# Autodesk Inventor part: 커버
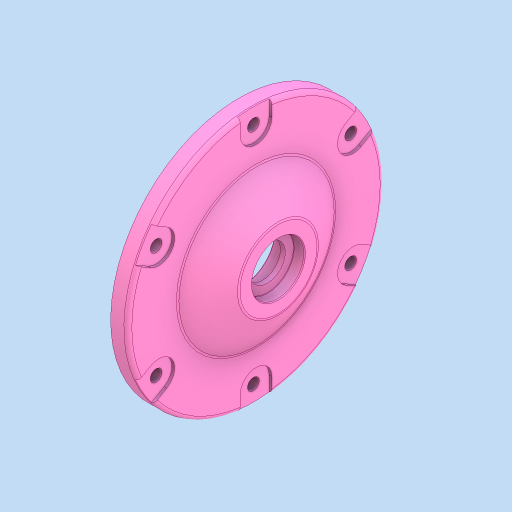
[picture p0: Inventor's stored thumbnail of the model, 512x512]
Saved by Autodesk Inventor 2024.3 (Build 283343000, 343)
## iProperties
Created: 2025-11
Part Number: 커버
Material: 알루미늄 6061
Document SubType Name: Modeling
Designer: PC2-03
Density: 2.7 g/cm^3
Appearance: 기본값
Author: jhkim
Sending System: Autodesk Inventor 2026
Preprocessor: ST-DEVELOPER v20.1
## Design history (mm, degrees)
feature "솔리드1"
node "솔리드2"
